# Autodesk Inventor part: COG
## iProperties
Author: Neil
Shininess: 42.0
Angle Display Precision: 2
Document Length Units: 11272
Document Angle Units: 11286
Document Time Units: 11279
Document Mass Units: 11290
Document Length Units Precision: 3
Document Angle Units Precision: 2
Compacted: True
PropertySet Name: _Private Model Information
Created: 2001-09
Part Number: COG
Material: COG
Document SubType Name: Modeling
Designer: Neil
Control State: 0
Master: False
Checked Out: False
PropertySet Name: Design Tracking Control
Density: 0.0
Volumn: 10.948333144675047
Area: 34.905853618063105
PropertySet Name: Model Information
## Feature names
1. Revolution1
2. Extrusion1
3. Circular Pattern1
4. Circular Pattern2
5. Chamfer1
